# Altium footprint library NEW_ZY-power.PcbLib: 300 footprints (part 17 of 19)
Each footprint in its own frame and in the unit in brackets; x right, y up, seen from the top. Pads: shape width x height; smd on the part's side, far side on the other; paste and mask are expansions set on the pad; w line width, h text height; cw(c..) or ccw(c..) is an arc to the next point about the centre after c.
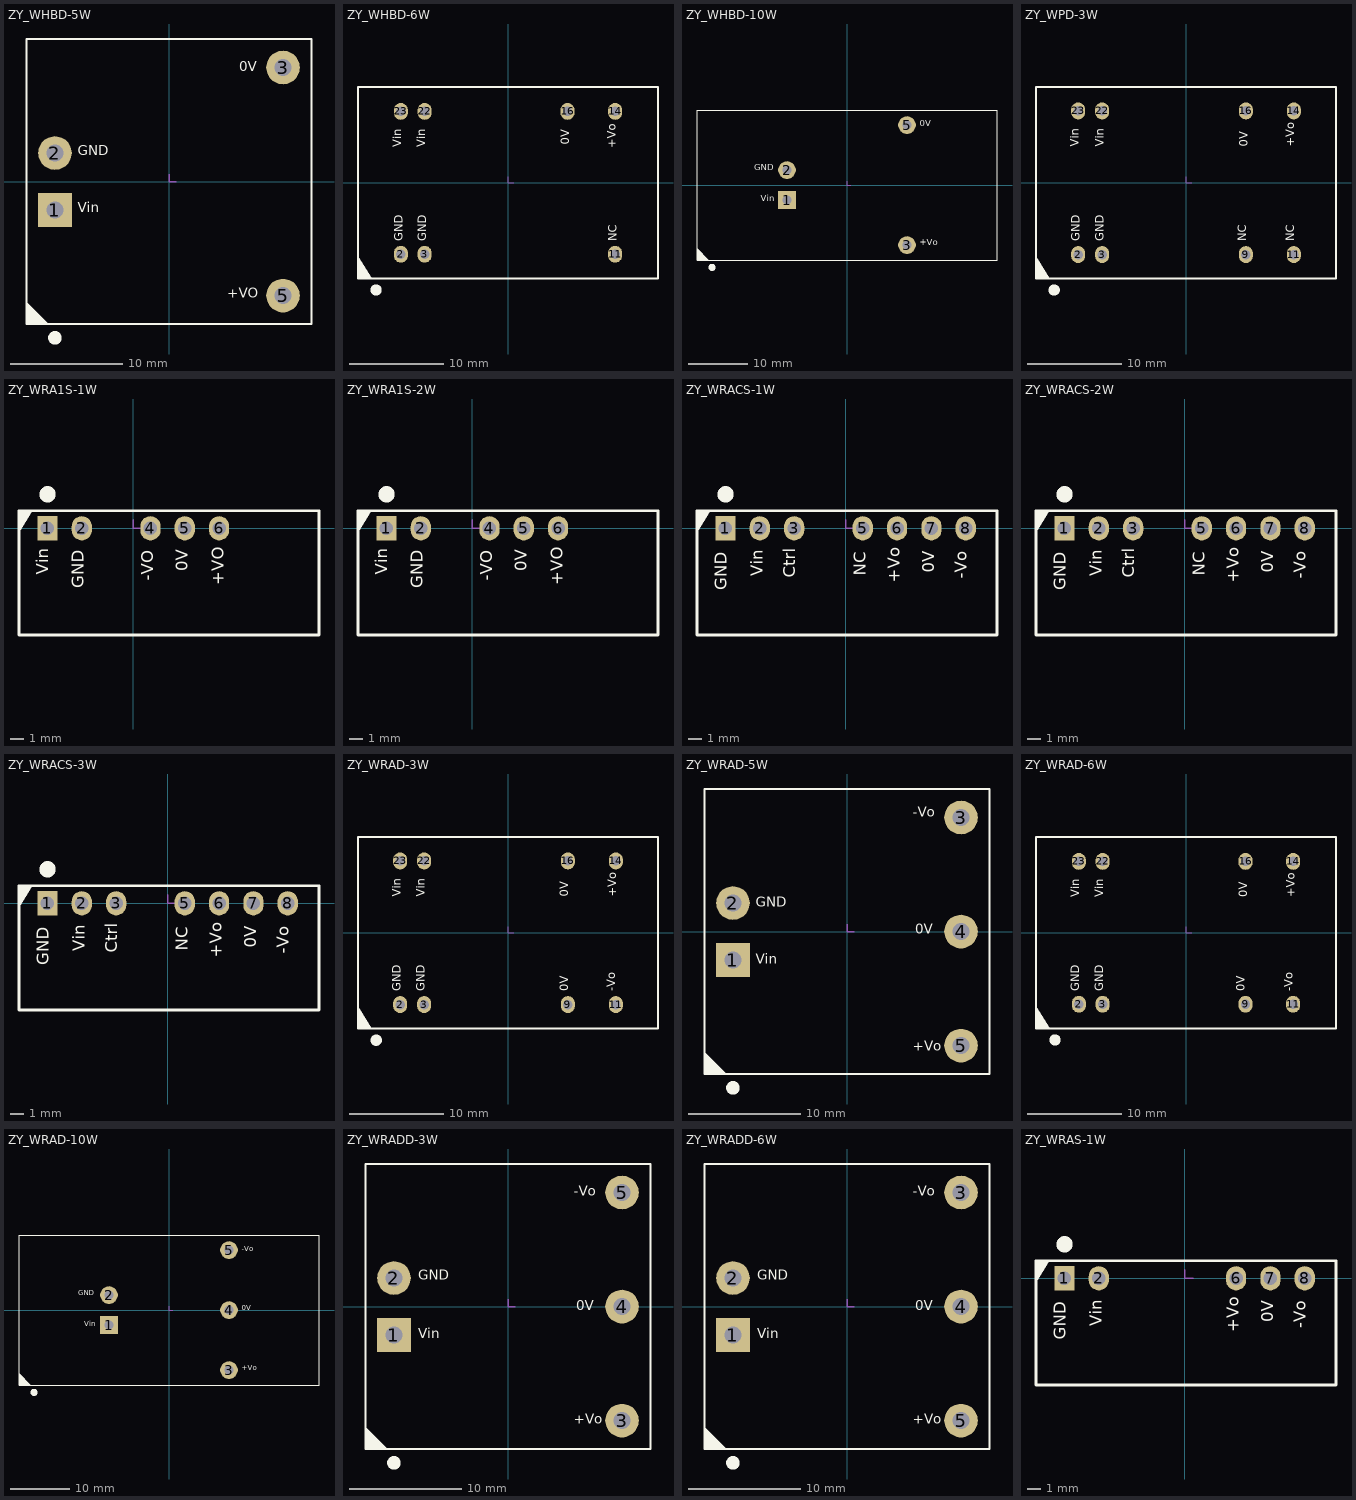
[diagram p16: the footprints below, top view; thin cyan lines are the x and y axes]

## ZY_WHBD-5W [mm]
height 11.7
pads (4):
  rect 3x3 hole 1.5: 1(-10.16,-2.54)
  round 3 hole 1.5: 2(-10.16,2.54) 3(10.16,10.16) 5(10.16,-10.16)
Top Overlay:
  circle w1: c-10.16,-13.925 r0.1
  region: -12.7,-12.7 -10.725,-12.7 -12.7,-10.725
  lines w0.2: -12.7,-12.7 12.7,-12.7 12.7,12.7 -12.7,12.7 -12.7,-12.7
  text "0V" at 6.238,9.525 h1.52
  text "+VO" at 5.207,-10.668 h1.52
  text "Vin" at -8.128,-3.048 h1.52
  text "GND" at -8.128,2.032 h1.52
Mechanical 15:
  lines w0.127: 0,0.635 0,0 0.635,0

## ZY_WHBD-6W [mm]
height 10.5
pads (7):
  oval 1.5x1.8 hole 1: 2(-11.43,-7.62) 3(-8.89,-7.62) 11(11.43,-7.62) 14(11.43,7.62) 16(6.35,7.62) 22(-8.89,7.62) 23(-11.43,7.62)
Top Overlay:
  circle w1: c-14.07,-11.425 r0.1
  region: -16,-7.87 -16,-10.2 -14.54,-10.2
  lines w0.2: -16,-10.2 16,-10.2 16,10.2 -16,10.2 -16,-10.2
  text "0V" at 6.858,4.064 h1.52
  text "+Vo" at 11.811,3.683 h1.52
  text "NC" at 11.938,-6.223 h1.52
  text "Vin" at -8.509,3.81 h1.52
  text "Vin" at -11.049,3.81 h1.52
  text "GND" at -8.382,-6.223 h1.52
  text "GND" at -10.922,-6.223 h1.52
Mechanical 15:
  lines w0.127: 0,0.635 0,0 0.635,0

## ZY_WHBD-10W [mm]
pads (4):
  rect 3x3 hole 1.5: 1(-10.16,-2.54)
  round 3 hole 1.5: 2(-10.16,2.54) 3(10.16,-10.16) 5(10.16,10.16)
Top Overlay:
  circle w1: c-22.86,-13.925 r0.1
  region: -25.4,-12.7 -23.425,-12.7 -25.4,-10.725
  lines w0.2: -25.4,-12.7 -25.4,12.7 25.4,12.7 25.4,-12.7 -25.4,-12.7
  text "+Vo" at 12.319,-10.541 h1.78
  text "0V" at 12.319,9.652 h1.78
  text "GND" at -15.748,2.159 h1.78
  text "Vin" at -14.568,-3.048 h1.78
Mechanical 15:
  lines w0.127: 0,0.635 0,0 0.635,0

## ZY_WPD-3W [mm] "宽压输入非隔离稳压单输出"
height 9.5
pads (8):
  oval 1.5x1.8 hole 1: 2(-11.43,-7.62) 3(-8.89,-7.62) 9(6.35,-7.62) 11(11.43,-7.62) 14(11.43,7.62) 16(6.35,7.62) 22(-8.89,7.62) 23(-11.43,7.62)
Top Overlay:
  circle w1: c-13.97,-11.375 r0.1
  region: -15.9,-7.82 -15.9,-10.15 -14.44,-10.15
  lines w0.2: -15.9,-10.15 -15.9,10.15 15.9,10.15 15.9,-10.15 -15.9,-10.15
  text "GND" at -10.922,-6.223 h1.52
  text "GND" at -8.382,-6.223 h1.52
  text "NC" at 6.731,-6.223 h1.52
  text "NC" at 11.811,-6.223 h1.52
  text "+Vo" at 11.811,3.81 h1.52
  text "0V" at 6.858,3.81 h1.52
  text "Vin" at -8.382,3.81 h1.52
  text "Vin" at -11.049,3.81 h1.52
Mechanical 15:
  lines w0.127: 0,0.635 0,0 0.635,0

## ZY_WRA1S-1W [mm]
height 12.2
pads (5):
  rect 1.5x1.8 hole 1: 1(-6.35,0)
  oval 1.5x1.8 hole 1: 2(-3.81,0) 4(1.27,0) 5(3.81,0) 6(6.35,0)
Top Overlay:
  circle w1: c-6.35,2.52 r0.1
  region: -8.458,-0.29 -8.458,1.295 -7.465,1.295
  lines w0.2: 13.741,-7.899 -8.458,-7.899 -8.458,1.295 13.741,1.295 13.741,-7.874
  text "GND" at -3.353,-4.445 h1.52
  text "Vin" at -5.994,-3.435 h1.52
  text "+VO" at 6.985,-4.194 h1.52
  text "0V" at 4.343,-3.163 h1.52
  text "-VO" at 1.778,-3.882 h1.52
Mechanical 15:
  lines w0.127: 0,0.635 0,0 0.635,0

## ZY_WRA1S-2W [mm]
height 12.2
pads (5):
  rect 1.5x1.8 hole 1: 1(-6.35,0)
  oval 1.5x1.8 hole 1: 2(-3.81,0) 4(1.27,0) 5(3.81,0) 6(6.35,0)
Top Overlay:
  circle w1: c-6.35,2.52 r0.1
  region: -8.458,-0.29 -8.458,1.295 -7.465,1.295
  lines w0.2: 13.741,-7.899 -8.458,-7.899 -8.458,1.295 13.741,1.295 13.741,-7.874
  text "GND" at -3.353,-4.445 h1.52
  text "Vin" at -5.994,-3.435 h1.52
  text "+VO" at 6.985,-4.194 h1.52
  text "0V" at 4.343,-3.163 h1.52
  text "-VO" at 1.778,-3.882 h1.52
Mechanical 15:
  lines w0.127: 0,0.635 0,0 0.635,0

## ZY_WRACS-1W [mm]
height 12.2
pads (7):
  rect 1.5x1.8 hole 1: 1(-8.89,0)
  oval 1.5x1.8 hole 1: 2(-6.35,0) 3(-3.81,0) 5(1.27,0) 6(3.81,0) 7(6.35,0) 8(8.89,0)
Top Overlay:
  circle w1: c-8.89,2.52 r0.1
  region: -10.998,-0.29 -10.998,1.295 -10.005,1.295
  lines w0.2: 11.201,-7.899 -10.998,-7.899 -10.998,1.295 11.201,1.295 11.201,-7.874
  text "-Vo" at 9.271,-3.718 h1.52
  text "0V" at 6.858,-3.29 h1.52
  text "+Vo" at 4.318,-4.03 h1.52
  text "NC" at 1.778,-3.501 h1.52
  text "Ctrl" at -3.429,-3.646 h1.52
  text "Vin" at -5.842,-3.562 h1.52
  text "GND" at -8.509,-4.572 h1.52
Mechanical 15:
  lines w0.127: 0,0.635 0,0 0.635,0

## ZY_WRACS-2W [mm]
pads (7):
  rect 1.5x1.8 hole 1: 1(-8.89,0)
  oval 1.5x1.8 hole 1: 2(-6.35,0) 3(-3.81,0) 5(1.27,0) 6(3.81,0) 7(6.35,0) 8(8.89,0)
Top Overlay:
  circle w1: c-8.89,2.52 r0.1
  region: -10.998,-0.29 -10.998,1.295 -10.005,1.295
  lines w0.2: 11.201,-7.899 -10.998,-7.899 -10.998,1.295 11.201,1.295 11.201,-7.874
  text "GND" at -8.509,-4.572 h1.52
  text "Vin" at -5.842,-3.562 h1.52
  text "Ctrl" at -3.429,-3.646 h1.52
  text "NC" at 1.778,-3.501 h1.52
  text "+Vo" at 4.318,-4.03 h1.52
  text "0V" at 6.858,-3.29 h1.52
  text "-Vo" at 9.271,-3.718 h1.52
Mechanical 15:
  lines w0.127: 0,0.635 0,0 0.635,0

## ZY_WRACS-3W [mm]
height 12.2
pads (7):
  rect 1.5x1.8 hole 1: 1(-8.89,0)
  oval 1.5x1.8 hole 1: 2(-6.35,0) 3(-3.81,0) 5(1.27,0) 6(3.81,0) 7(6.35,0) 8(8.89,0)
Top Overlay:
  circle w1: c-8.89,2.52 r0.1
  region: -10.998,-0.29 -10.998,1.295 -10.005,1.295
  lines w0.2: 11.201,-7.899 -10.998,-7.899 -10.998,1.295 11.201,1.295 11.201,-7.874
  text "GND" at -8.509,-4.572 h1.52
  text "Vin" at -5.842,-3.562 h1.52
  text "Ctrl" at -3.429,-3.646 h1.52
  text "NC" at 1.778,-3.501 h1.52
  text "+Vo" at 4.318,-4.03 h1.52
  text "0V" at 6.858,-3.29 h1.52
  text "-Vo" at 9.271,-3.718 h1.52
Mechanical 15:
  lines w0.127: 0,0.635 0,0 0.635,0

## ZY_WRAD-3W [mm]
pads (8):
  oval 1.5x1.8 hole 1: 2(-11.43,-7.62) 3(-8.89,-7.62) 9(6.35,-7.62) 11(11.43,-7.62) 14(11.43,7.62) 16(6.35,7.62) 22(-8.89,7.62) 23(-11.43,7.62)
Top Overlay:
  circle w1: c-13.97,-11.385 r0.1
  region: -15.9,-7.83 -15.9,-10.16 -14.44,-10.16
  lines w0.2: -15.9,-10.16 15.9,-10.16 15.9,10.16 -15.9,10.16 -15.9,-10.16
  text "GND" at -11.049,-6.223 h1.52
  text "GND" at -8.509,-6.223 h1.52
  text "0V" at 6.731,-6.223 h1.52
  text "-Vo" at 11.684,-6.223 h1.52
  text "+Vo" at 11.811,3.81 h1.52
  text "0V" at 6.731,3.81 h1.52
  text "Vin" at -8.509,3.81 h1.52
  text "Vin" at -11.049,3.81 h1.52
Mechanical 15:
  lines w0.127: 0,0.635 0,0 0.635,0

## ZY_WRAD-5W [mm]
height 11.7
pads (5):
  rect 3x3 hole 1.5: 1(-10.16,-2.54)
  round 3 hole 1.5: 2(-10.16,2.54) 3(10.16,10.16) 4(10.16,0) 5(10.16,-10.16)
Top Overlay:
  circle w1: c-10.16,-13.925 r0.1
  region: -12.7,-12.7 -10.725,-12.7 -12.7,-10.725
  lines w0.2: -12.7,-12.7 12.7,-12.7 12.7,12.7 -12.7,12.7 -12.7,-12.7
  text "-Vo" at 5.842,9.906 h1.52
  text "+Vo" at 5.842,-10.922 h1.52
  text "Vin" at -8.128,-3.175 h1.52
  text "GND" at -8.128,1.905 h1.52
  text "0V" at 6.096,-0.508 h1.52
Mechanical 15:
  lines w0.127: 0,0.635 0,0 0.635,0

## ZY_WRAD-6W [mm]
height 10.5
pads (8):
  oval 1.5x1.8 hole 1: 2(-11.43,-7.62) 3(-8.89,-7.62) 9(6.35,-7.62) 11(11.43,-7.62) 14(11.43,7.62) 16(6.35,7.62) 22(-8.89,7.62) 23(-11.43,7.62)
Top Overlay:
  circle w1: c-13.97,-11.425 r0.1
  region: -16,-7.87 -16,-10.2 -14.54,-10.2
  lines w0.2: -16,-10.2 -16,10.2 16,10.2 16,-10.2 -16,-10.2
  text "0V" at 6.604,-6.223 h1.52
  text "GND" at -11.049,-6.223 h1.52
  text "GND" at -8.509,-6.223 h1.52
  text "Vin" at -11.049,3.81 h1.52
  text "Vin" at -8.509,3.81 h1.52
  text "-Vo" at 11.684,-6.223 h1.52
  text "+Vo" at 11.938,3.81 h1.52
  text "0V" at 6.858,3.81 h1.52
Mechanical 15:
  lines w0.127: 0,0.635 0,0 0.635,0

## ZY_WRAD-10W [mm]
pads (5):
  rect 3x3 hole 1.5: 1(-10.16,-2.54)
  round 3 hole 1.5: 2(-10.16,2.54) 3(10.16,-10.16) 4(10.16,0) 5(10.16,10.16)
Top Overlay:
  circle w1: c-22.86,-13.925 r0.1
  region: -25.4,-12.7 -23.425,-12.7 -25.4,-10.725
  lines w0.2: -25.4,-12.7 -25.4,12.7 25.4,12.7 25.4,-12.7 -25.4,-12.7
  text "-Vo" at 12.319,9.652 h1.52
  text "+Vo" at 12.319,-10.541 h1.52
  text "0V" at 12.319,-0.381 h1.52
  text "GND" at -15.367,2.159 h1.52
  text "Vin" at -14.357,-3.048 h1.52
Mechanical 15:
  lines w0.127: 0,0.635 0,0 0.635,0

## ZY_WRADD-3W [mm]
height 11.7
pads (5):
  rect 3x3 hole 1.5: 1(-10.16,-2.54)
  round 3 hole 1.5: 2(-10.16,2.54) 3(10.16,-10.16) 4(10.16,0) 5(10.16,10.16)
Top Overlay:
  circle w1: c-10.16,-13.925 r0.1
  region: -12.7,-12.7 -10.725,-12.7 -12.7,-10.725
  lines w0.2: -12.7,-12.7 -12.7,12.7 12.7,12.7 12.7,-12.7 -12.7,-12.7
  text "0V" at 6.096,-0.635 h1.52
  text "GND" at -8.002,2.057 h1.52
  text "Vin" at -8.001,-3.15 h1.52
  text "+Vo" at 5.842,-10.744 h1.52
  text "-Vo" at 5.842,9.576 h1.52
Mechanical 15:
  lines w0.127: 0,0.635 0,0 0.635,0

## ZY_WRADD-6W [mm]
height 11.7
pads (5):
  rect 3x3 hole 1.5: 1(-10.16,-2.54)
  round 3 hole 1.5: 2(-10.16,2.54) 3(10.16,10.16) 4(10.16,0) 5(10.16,-10.16)
Top Overlay:
  circle w1: c-10.16,-13.925 r0.1
  region: -12.7,-12.7 -10.725,-12.7 -12.7,-10.725
  lines w0.2: -12.7,-12.7 -12.7,12.7 12.7,12.7 12.7,-12.7 -12.7,-12.7
  text "-Vo" at 5.842,9.576 h1.52
  text "+Vo" at 5.842,-10.744 h1.52
  text "Vin" at -8.001,-3.15 h1.52
  text "GND" at -8.001,2.057 h1.52
  text "0V" at 6.096,-0.635 h1.52
Mechanical 15:
  lines w0.127: 0,0.635 0,0 0.635,0

## ZY_WRAS-1W [mm]
height 12.2
pads (5):
  rect 1.5x1.8 hole 1: 1(-8.89,0)
  oval 1.5x1.8 hole 1: 2(-6.35,0) 6(3.81,0) 7(6.35,0) 8(8.89,0)
Top Overlay:
  circle w1: c-8.89,2.52 r0.1
  region: -10.998,-0.29 -10.998,1.295 -10.005,1.295
  lines w0.2: 11.201,-7.899 -10.998,-7.899 -10.998,1.295 11.201,1.295 11.201,-7.874
  text "GND" at -8.509,-4.547 h1.52
  text "Vin" at -5.842,-3.536 h1.52
  text "+Vo" at 4.318,-4.004 h1.52
  text "0V" at 6.858,-3.264 h1.52
  text "-Vo" at 9.271,-3.692 h1.52
Mechanical 15:
  lines w0.127: 0,0.635 0,0 0.635,0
